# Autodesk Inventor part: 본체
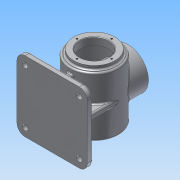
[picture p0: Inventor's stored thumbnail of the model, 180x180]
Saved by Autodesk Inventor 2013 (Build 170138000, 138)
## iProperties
Created: 2015-07
Part Number: 본체
Material: 알루미늄 6061
Document SubType Name: Modeling
Designer: Administrator
Density: 2.71 g/cm^3
Mass: 1277.74 g
Surface Area: 1267.61 cm^2
Volume: 471.49 cm^3
Author: Administrator
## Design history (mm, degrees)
sketch "스케치1"
  geometry: C1 r 45 at (0, 0); 1 further point
  constraints: 1 centre point, 1 coincident
  dimensions: "d0" = 90 diameter of C1
extrude "돌출1" new body sketch "스케치1" stored distance "d1" = 110; taper "d2" = 0 deg
sketch "스케치2"
  geometry: L1 (-65, -68)-(65, -68); L2 (65, -68)-(65, -78); L3 (65, -78)-(-65, -78); L4 (-65, -78)-(-65, -68); 2 further points
  constraints: 8 end point, 2 parallel, 1 horizontal, 1 midpoint, 1 perpendicular, 1 vertical alignment
  dimensions: "d3" = 130 distance of L2.end L3.end; "d5" = 10 distance of L1.end L2.end; "d6" = 78 distance from line of L3 point (0, 0)
extrude "돌출2" join sketch "스케치2" stored distance "d7" = 130; taper "d8" = 0 deg
sketch "스케치3"
  geometry: L1 (130, 0)-(130, 130) reference; L2 (0, 130)-(130, 130) reference; L3 (60, 70)-(60, 110); L4 (60, 110)-(70, 110); L5 (70, 110)-(70, 70); L6 (70, 70)-(110, 70); L7 (110, 70)-(110, 60); L8 (110, 60)-(70, 60); L9 (70, 60)-(70, 20); L10 (70, 20)-(60, 20); L11 (60, 20)-(60, 60); L12 (60, 60)-(20, 60); L13 (20, 60)-(20, 70); L14 (20, 70)-(60, 70); L15 (0, 130)-(130, 130) reference; L16 (130, 130)-(130, 0) reference; L17 (130, 0)-(0, 0) reference; L18 (0, 0)-(0, 130) reference; C1 r 7.5 at (15, 115); C2 r 7.5 at (115, 115); C3 r 7.5 at (15, 15); C4 r 7.5 at (115, 15); 3 further points
  constraints: 24 end point, 8 parallel, 5 equal length, 4 centre point, 3 horizontal alignment, 3 perpendicular, 3 vertical alignment, 2 collinear, 2 midpoint
  dimensions: "d9" = 10 distance of L3.end L4.end; "d11" = 10 distance of L6.end L7.end; "d12" = 90 distance between parallel lines of L10 L4; "d13" = 90 distance between parallel lines of L7 L13; "d14" = 15 diameter of C1; "d15" = 15 diameter of C2; "d16" = 15 diameter of C3; "d17" = 15 diameter of C4; "d18" = 100 distance of C2.centre C1.centre; "d19" = 100 distance of C4.centre C2.centre; "d20" = 15 distance from line of L1 C2.centre; "d21" = 15 distance from line of L15 C2.centre
  node "절단 모서리 투영1"
extrude "돌출3" join sketch "스케치3" stored distance "d22" = 130; taper "d23" = 0 deg
extrude "돌출4" join sketch "스케치3" distance "d24" = 3; taper "d25" = 0 deg
hole "구멍1" diameter "d28" = 10; stored, may be unused: countersink angle "d32" = 90 deg, drill point angle "d34" = 118 deg; dims "d26" = 10, "d27" = 10, "d29" = 6, "d30" = 4, "d31" = 2, "d33" = 8
hole "구멍2" diameter "d37" = 10; stored, may be unused: countersink angle "d41" = 90 deg, drill point angle "d43" = 118 deg; dims "d35" = 10, "d36" = 10, "d38" = 6, "d39" = 4, "d40" = 2, "d42" = 8
hole "구멍3" diameter "d46" = 10; stored, may be unused: countersink angle "d50" = 90 deg, drill point angle "d52" = 118 deg; dims "d44" = 10, "d45" = 10, "d47" = 6, "d48" = 4, "d49" = 2, "d51" = 8
hole "구멍4" diameter "d55" = 10; stored, may be unused: countersink angle "d59" = 90 deg, drill point angle "d61" = 118 deg; dims "d53" = 10, "d54" = 10, "d56" = 6, "d57" = 4, "d58" = 2, "d60" = 8
sketch "스케치4"
  geometry: C1 r 45 at (0, 0) reference; C2 r 38 at (0, 0)
  constraints: 1 centre point, 1 coincident
  dimensions: "d62" = 76 diameter of C2
extrude "돌출5" join sketch "스케치4" distance "d63" = 7; taper "d64" = 0 deg
node "작업 평면1"
sketch "스케치5"
  geometry: L1 (-45, -55)-(45, -55) reference; C1 r 38 at (0, 0); 1 further point
  constraints: 1 centre point, 1 coincident
  dimensions: "d66" = 76 diameter of C1
extrude "돌출6" join sketch "스케치5" stored distance "d67" = 7; taper "d68" = 0 deg
sketch "스케치6"
  geometry: C1 r 38 at (0, 0) reference; C2 r 27 at (0, 0)
  constraints: 1 centre point, 1 coincident
  dimensions: "d69" = 54 diameter of C2
extrude "돌출7" cut sketch "스케치6" distance "d70" = 14; taper "d71" = 0 deg
sketch "스케치7"
  geometry: C1 r 27 at (0, 0) reference; C2 r 40 at (0, 0)
  constraints: 1 centre point, 1 coincident
  dimensions: "d72" = 80 diameter of C2
extrude "돌출8" cut sketch "스케치7" distance "d73" = 96; taper "d74" = 0 deg
sketch "스케치8"
  geometry: C1 r 38 at (0, 0) reference; C2 r 27 at (0, 0)
  constraints: 1 centre point, 1 coincident
  dimensions: "d75" = 54 diameter of C2
extrude "돌출9" cut sketch "스케치8" stored distance "d76" = 96; taper "d77" = 0 deg
sketch "스케치9"
  geometry: C1 r 27 at (0, 0) reference; C2 r 38 at (0, 0) reference; A1 r 32 centre (0, 0) between (0, 32) and (0, 32); 4 further points
  constraints: 6 point on circle, 4 vertical alignment, 2 horizontal alignment, 1 centre point, 1 coincident
  dimensions: "d78" = 64 diameter of A1
hole "구멍5" sketch "스케치9" at (0, 32), (0, -32), (-32, 0), (32, 0) diameter "d79" = 3.242; stored, may be unused: countersink angle "d83" = 90 deg, drill point angle "d85" = 118 deg; dims "d80" = 8, "d81" = 4, "d82" = 2, "d84" = 10
sketch "스케치10"
  geometry: C1 r 27 at (0, 0) reference; C2 r 38 at (0, 0) reference; A1 r 32 centre (0, 0) between (0, 32) and (-32, 0); 2 further points
  constraints: 4 point on circle, 2 horizontal alignment, 2 vertical alignment, 1 centre point, 1 coincident
  dimensions: "d86" = 64 diameter of A1
hole "구멍6" sketch "스케치10" at (0, 32), (-32, 0), (0, -32), (32, 0) diameter "d87" = 3.242; stored, may be unused: countersink angle "d91" = 90 deg, drill point angle "d93" = 118 deg; dims "d88" = 8, "d89" = 4, "d90" = 2, "d92" = 10
fillet "모깎기1" dims "d94" = 3
fillet "모깎기2" dims "d95" = 3
fillet "모깎기3" dims "d96" = 3
fillet "모깎기4" dims "d97" = 3
fillet "모깎기5" dims "d98" = 3
fillet "모깎기6" dims "d99" = 3
fillet "모깎기7" dims "d100" = 3
fillet "모깎기8" dims "d101" = 3
fillet "모깎기9" dims "d102" = 3
fillet "모깎기10" dims "d103" = 3
fillet "모깎기11" dims "d104" = 3
fillet "모깎기12" dims "d105" = 15
fillet "모깎기13" dims "d106" = 3
chamfer "모따기1" distance "d107" = 1; stored, may be unused: second distance "d108" = 2, angle "d109" = 45 deg
sketch "스케치11"
  geometry: C1 r 42 at (0, 0) reference; 1 further point
  constraints: 1 coincident, 1 other
feature "엠보싱1" sketch "스케치11" dims "d0" = 90, "d9" = 10, "d11" = 10, "d12" = 90, "d13" = 90, "d110" = 0.5, "d111" = 0
node "솔리드1"
other parameters: "d65" = 62
